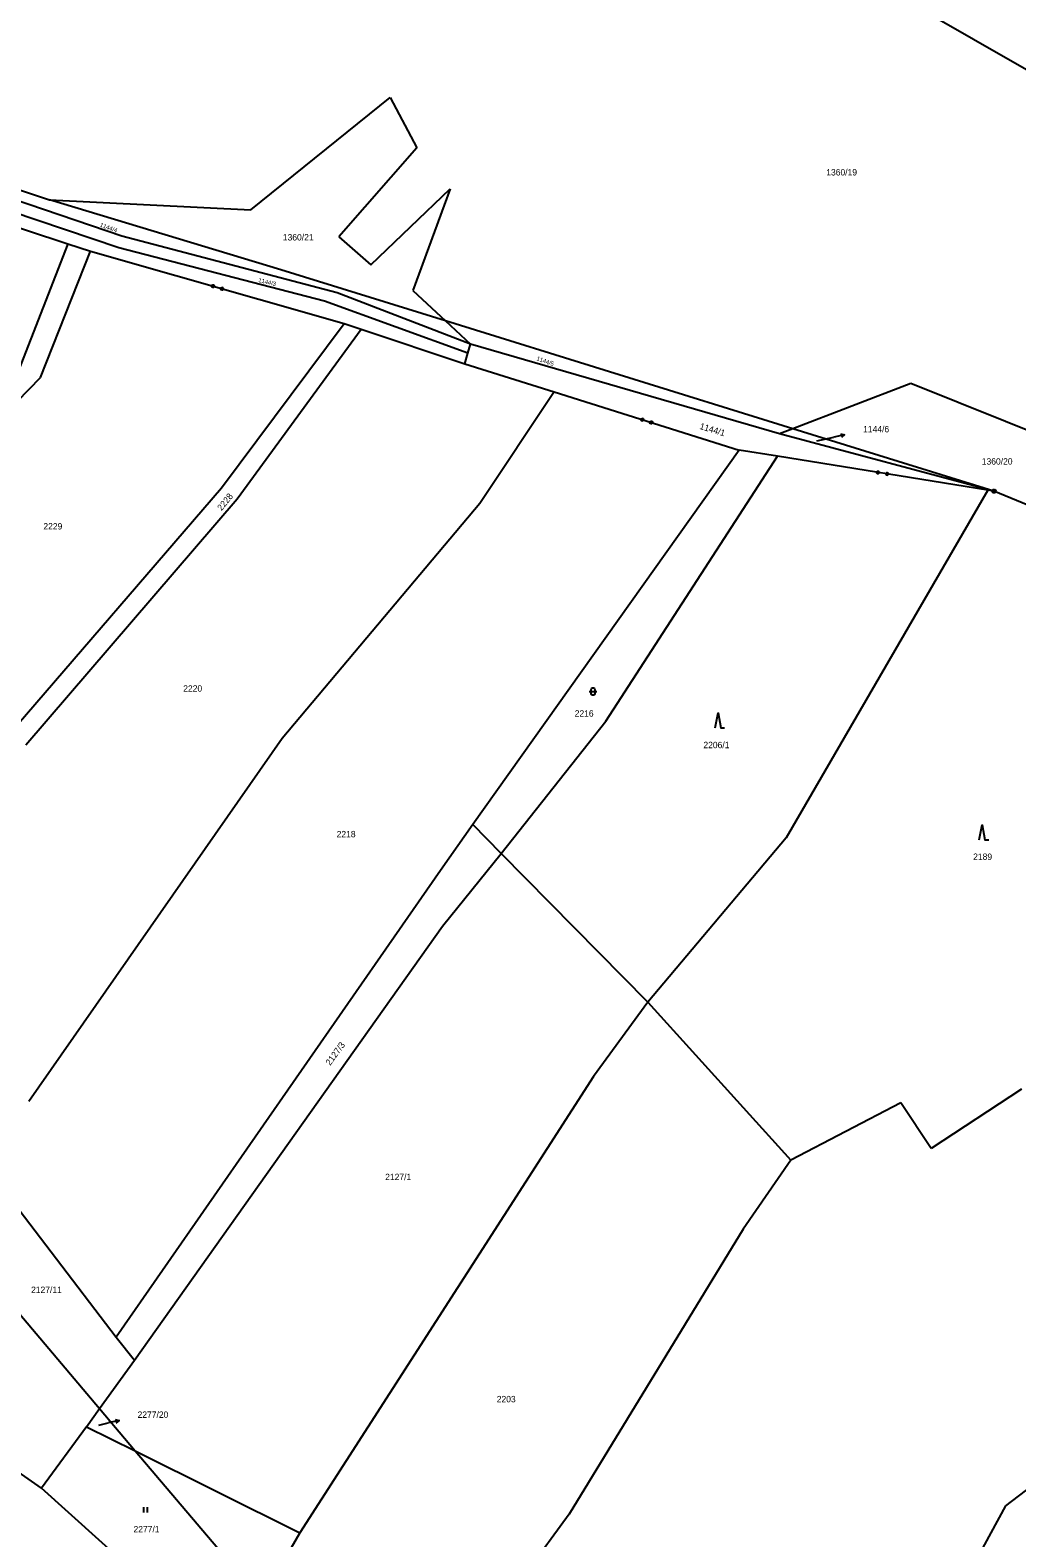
# Model space of a CAD drawing. Extents: x -747792 to -745414, y -1093712 to -1091463.
# Drawn here: x -746345.7 to -746213.9, y -1092850.4 to -1092649.1 of the extents above; entities that cross this region are included whole.
import ezdxf

# ---------------------------------------------------------------- set-up
doc = ezdxf.new("R2010")
doc.units = 0
for name, color, linetype in [('Pracovní_bod JDTM STC_VC', 7, 'Continuous'), ('Pracovní_bod JDTM STC_VC - číslo', 7, 'Continuous'), ('Pracovní_bod NN - výška', 7, 'Continuous'), ('Pracovní_bod polohopisu - výška', 7, 'Continuous'), ('Pracovní_bod VN - výška', 7, 'Continuous')]:
    doc.layers.add(name, color=color, linetype=linetype)

msp = doc.modelspace()

# ---------------------------------------------------------------- linework, layer by layer
at = {"layer": 'Pracovní_bod JDTM STC_VC - číslo'}
for points in [[(-746270.99, -1092737.4), (-746270.35, -1092737.4), (-746269.99, -1092737.4)], [(-746254.16, -1092742.26), (-746253.78, -1092740.26), (-746253.41, -1092742.26), (-746252.91, -1092742.26)], [(-746218.9, -1092757.18), (-746218.52, -1092755.18), (-746218.15, -1092757.18), (-746217.65, -1092757.18)], [(-746330.51, -1092846.31), (-746330.51, -1092847.06)], [(-746330.01, -1092847.06), (-746330.01, -1092846.31)]]:
    msp.add_lwpolyline(points, dxfattribs=at)
msp.add_lwpolyline([(-746270.74, -1092737.15), (-746270.69, -1092737.01), (-746270.57, -1092736.92), (-746270.41, -1092736.92), (-746270.28, -1092737.01), (-746270.23, -1092737.15), (-746270.23, -1092737.65), (-746270.28, -1092737.79), (-746270.41, -1092737.88), (-746270.57, -1092737.88), (-746270.69, -1092737.79), (-746270.74, -1092737.65)], close=True, dxfattribs=at)
at = {"layer": 'Pracovní_bod NN - výška'}
for points in [[(-746138.26, -1092696.87), (-746328.04, -1092588.27)], [(-746333.4, -1092676.58), (-746383.28, -1092659.63)], [(-746382.43, -1092658.53), (-746343.09, -1092671.73)], [(-746316.2, -1092673.08), (-746297.59, -1092658.05)], [(-746297.59, -1092658.05), (-746294, -1092664.76)], [(-746333.8, -1092678.12), (-746384.12, -1092661.15)], [(-746385.1, -1092662.91), (-746340.63, -1092677.59)], [(-746385.1, -1092662.91), (-746340.63, -1092677.59)], [(-746294, -1092664.76), (-746304.42, -1092676.67)], [(-746343.09, -1092671.73), (-746316.2, -1092673.08)], [(-746312.2, -1092681.06), (-746343.09, -1092671.73)], [(-746300.15, -1092680.41), (-746289.57, -1092670.24)], [(-746289.57, -1092670.24), (-746294.55, -1092683.83)], [(-746340.63, -1092677.59), (-746347.23, -1092694.52)], [(-746340.63, -1092677.59), (-746337.61, -1092678.59)], [(-746340.63, -1092677.59), (-746337.61, -1092678.59)], [(-746304.67, -1092684.13), (-746333.4, -1092676.58)], [(-746304.42, -1092676.67), (-746300.15, -1092680.41)], [(-746344.28, -1092695.45), (-746337.61, -1092678.59)], [(-746337.61, -1092678.59), (-746303.71, -1092688.24)], [(-746337.61, -1092678.59), (-746303.71, -1092688.24)], [(-746306.34, -1092685.25), (-746333.8, -1092678.12)], [(-746290.18, -1092687.9), (-746312.2, -1092681.06)], [(-746321.13, -1092683.11), (-746321.07, -1092683.23), (-746321.1, -1092683.36), (-746321.22, -1092683.43), (-746321.35, -1092683.39), (-746321.41, -1092683.27), (-746321.38, -1092683.14), (-746321.26, -1092683.08), (-746321.13, -1092683.11), (-746321.14, -1092683.13), (-746321.26, -1092683.1), (-746321.31, -1092683.13), (-746321.11, -1092683.18), (-746321.09, -1092683.23), (-746321.36, -1092683.15), (-746321.37, -1092683.19), (-746321.1, -1092683.27), (-746321.11, -1092683.31), (-746321.38, -1092683.23), (-746321.39, -1092683.27), (-746321.12, -1092683.35), (-746321.17, -1092683.37), (-746321.36, -1092683.32), (-746321.33, -1092683.37), (-746321.22, -1092683.4)], [(-746321.13, -1092683.11), (-746321.07, -1092683.23), (-746321.1, -1092683.36), (-746321.22, -1092683.43), (-746321.35, -1092683.39), (-746321.41, -1092683.27), (-746321.38, -1092683.14), (-746321.26, -1092683.08), (-746321.13, -1092683.11), (-746321.14, -1092683.13), (-746321.26, -1092683.1), (-746321.31, -1092683.13), (-746321.11, -1092683.18), (-746321.09, -1092683.23), (-746321.36, -1092683.15), (-746321.37, -1092683.19), (-746321.1, -1092683.27), (-746321.11, -1092683.31), (-746321.38, -1092683.23), (-746321.39, -1092683.27), (-746321.12, -1092683.35), (-746321.17, -1092683.37), (-746321.36, -1092683.32), (-746321.33, -1092683.37), (-746321.22, -1092683.4)], [(-746319.93, -1092683.46), (-746319.86, -1092683.57), (-746319.9, -1092683.7), (-746320.02, -1092683.77), (-746320.15, -1092683.73), (-746320.21, -1092683.62), (-746320.18, -1092683.49), (-746320.06, -1092683.42), (-746319.93, -1092683.46), (-746319.95, -1092683.47), (-746320.06, -1092683.44), (-746320.11, -1092683.47), (-746319.92, -1092683.52), (-746319.89, -1092683.57), (-746320.16, -1092683.49), (-746320.17, -1092683.53), (-746319.9, -1092683.61), (-746319.92, -1092683.65), (-746320.18, -1092683.57), (-746320.2, -1092683.61), (-746319.93, -1092683.69), (-746319.98, -1092683.71), (-746320.17, -1092683.66), (-746320.14, -1092683.71), (-746320.03, -1092683.74)], [(-746319.93, -1092683.46), (-746319.86, -1092683.57), (-746319.9, -1092683.7), (-746320.02, -1092683.77), (-746320.15, -1092683.73), (-746320.21, -1092683.62), (-746320.18, -1092683.49), (-746320.06, -1092683.42), (-746319.93, -1092683.46), (-746319.95, -1092683.47), (-746320.06, -1092683.44), (-746320.11, -1092683.47), (-746319.92, -1092683.52), (-746319.89, -1092683.57), (-746320.16, -1092683.49), (-746320.17, -1092683.53), (-746319.9, -1092683.61), (-746319.92, -1092683.65), (-746320.18, -1092683.57), (-746320.2, -1092683.61), (-746319.93, -1092683.69), (-746319.98, -1092683.71), (-746320.17, -1092683.66), (-746320.14, -1092683.71), (-746320.03, -1092683.74)], [(-746287.19, -1092692.2), (-746306.34, -1092685.25)], [(-746286.85, -1092691), (-746304.67, -1092684.13)], [(-746294.55, -1092683.83), (-746290.18, -1092687.9)], [(-746320.11, -1092710.19), (-746303.71, -1092688.24)], [(-746318.02, -1092711.64), (-746301.45, -1092689)], [(-746303.71, -1092688.24), (-746301.45, -1092689)], [(-746303.71, -1092688.24), (-746301.45, -1092689)], [(-746301.45, -1092689), (-746287.61, -1092693.64)], [(-746301.45, -1092689), (-746287.61, -1092693.64)], [(-746290.18, -1092687.9), (-746286.85, -1092691)], [(-746243.81, -1092702.3), (-746290.18, -1092687.9)], [(-746287.19, -1092692.2), (-746286.85, -1092691)], [(-746245.6, -1092702.98), (-746286.85, -1092691)], [(-746287.61, -1092693.64), (-746287.19, -1092692.2)], [(-746287.61, -1092693.64), (-746275.7, -1092697.38)], [(-746287.61, -1092693.64), (-746275.7, -1092697.38)], [(-746368.82, -1092720.63), (-746344.28, -1092695.45)], [(-746275.7, -1092697.38), (-746285.63, -1092712.3)], [(-746275.7, -1092697.38), (-746250.98, -1092705.15)], [(-746275.7, -1092697.38), (-746250.98, -1092705.15)], [(-746228.03, -1092696.26), (-746243.81, -1092702.3)], [(-746196.64, -1092708.86), (-746228.03, -1092696.26)], [(-746263.8, -1092700.95), (-746263.74, -1092701.07), (-746263.78, -1092701.2), (-746263.9, -1092701.26), (-746264.03, -1092701.22), (-746264.09, -1092701.1), (-746264.05, -1092700.97), (-746263.93, -1092700.91), (-746263.8, -1092700.95), (-746263.81, -1092700.97), (-746263.93, -1092700.93), (-746263.98, -1092700.96), (-746263.79, -1092701.02), (-746263.76, -1092701.07), (-746264.03, -1092700.99), (-746264.04, -1092701.02), (-746263.77, -1092701.11), (-746263.78, -1092701.15), (-746264.05, -1092701.06), (-746264.06, -1092701.1), (-746263.8, -1092701.18), (-746263.85, -1092701.21), (-746264.04, -1092701.15), (-746264.01, -1092701.2), (-746263.9, -1092701.24)], [(-746263.8, -1092700.95), (-746263.74, -1092701.07), (-746263.78, -1092701.2), (-746263.9, -1092701.26), (-746264.03, -1092701.22), (-746264.09, -1092701.1), (-746264.05, -1092700.97), (-746263.93, -1092700.91), (-746263.8, -1092700.95), (-746263.81, -1092700.97), (-746263.93, -1092700.93), (-746263.98, -1092700.96), (-746263.79, -1092701.02), (-746263.76, -1092701.07), (-746264.03, -1092700.99), (-746264.04, -1092701.02), (-746263.77, -1092701.11), (-746263.78, -1092701.15), (-746264.05, -1092701.06), (-746264.06, -1092701.1), (-746263.8, -1092701.18), (-746263.85, -1092701.21), (-746264.04, -1092701.15), (-746264.01, -1092701.2), (-746263.9, -1092701.24)], [(-746262.61, -1092701.33), (-746262.55, -1092701.45), (-746262.59, -1092701.57), (-746262.71, -1092701.64), (-746262.84, -1092701.6), (-746262.9, -1092701.48), (-746262.86, -1092701.35), (-746262.74, -1092701.29), (-746262.61, -1092701.33), (-746262.63, -1092701.34), (-746262.74, -1092701.31), (-746262.79, -1092701.33), (-746262.6, -1092701.39), (-746262.58, -1092701.44), (-746262.85, -1092701.36), (-746262.86, -1092701.4), (-746262.59, -1092701.48), (-746262.6, -1092701.52), (-746262.87, -1092701.43), (-746262.88, -1092701.47), (-746262.61, -1092701.56), (-746262.66, -1092701.58), (-746262.85, -1092701.52), (-746262.83, -1092701.57), (-746262.71, -1092701.61)], [(-746262.61, -1092701.33), (-746262.55, -1092701.45), (-746262.59, -1092701.57), (-746262.71, -1092701.64), (-746262.84, -1092701.6), (-746262.9, -1092701.48), (-746262.86, -1092701.35), (-746262.74, -1092701.29), (-746262.61, -1092701.33), (-746262.63, -1092701.34), (-746262.74, -1092701.31), (-746262.79, -1092701.33), (-746262.6, -1092701.39), (-746262.58, -1092701.44), (-746262.85, -1092701.36), (-746262.86, -1092701.4), (-746262.59, -1092701.48), (-746262.6, -1092701.52), (-746262.87, -1092701.43), (-746262.88, -1092701.47), (-746262.61, -1092701.56), (-746262.66, -1092701.58), (-746262.85, -1092701.52), (-746262.83, -1092701.57), (-746262.71, -1092701.61)], [(-746243.81, -1092702.3), (-746245.6, -1092702.98)], [(-746216.96, -1092710.63), (-746245.6, -1092702.98)], [(-746216.96, -1092710.63), (-746243.81, -1092702.3)], [(-746250.98, -1092705.15), (-746286.54, -1092755.17)], [(-746268.8, -1092741.33), (-746245.86, -1092705.97)], [(-746245.86, -1092705.97), (-746250.98, -1092705.15)], [(-746245.86, -1092705.97), (-746250.98, -1092705.15)], [(-746217.76, -1092710.5), (-746245.86, -1092705.97)], [(-746217.76, -1092710.5), (-746245.86, -1092705.97)], [(-746232.54, -1092708.28), (-746232.62, -1092708.17), (-746232.6, -1092708.04), (-746232.49, -1092707.96), (-746232.36, -1092707.98), (-746232.28, -1092708.09), (-746232.3, -1092708.22), (-746232.41, -1092708.3), (-746232.54, -1092708.28), (-746232.52, -1092708.26), (-746232.4, -1092708.28), (-746232.36, -1092708.25), (-746232.56, -1092708.22), (-746232.59, -1092708.17), (-746232.31, -1092708.21), (-746232.31, -1092708.18), (-746232.58, -1092708.13), (-746232.58, -1092708.09), (-746232.3, -1092708.14), (-746232.29, -1092708.1), (-746232.57, -1092708.05), (-746232.52, -1092708.02), (-746232.33, -1092708.05), (-746232.36, -1092708), (-746232.48, -1092707.99)], [(-746232.54, -1092708.28), (-746232.62, -1092708.17), (-746232.6, -1092708.04), (-746232.49, -1092707.96), (-746232.36, -1092707.98), (-746232.28, -1092708.09), (-746232.3, -1092708.22), (-746232.41, -1092708.3), (-746232.54, -1092708.28), (-746232.52, -1092708.26), (-746232.4, -1092708.28), (-746232.36, -1092708.25), (-746232.56, -1092708.22), (-746232.59, -1092708.17), (-746232.31, -1092708.21), (-746232.31, -1092708.18), (-746232.58, -1092708.13), (-746232.58, -1092708.09), (-746232.3, -1092708.14), (-746232.29, -1092708.1), (-746232.57, -1092708.05), (-746232.52, -1092708.02), (-746232.33, -1092708.05), (-746232.36, -1092708), (-746232.48, -1092707.99)], [(-746231.31, -1092708.48), (-746231.39, -1092708.37), (-746231.36, -1092708.24), (-746231.26, -1092708.16), (-746231.12, -1092708.18), (-746231.04, -1092708.29), (-746231.07, -1092708.42), (-746231.17, -1092708.5), (-746231.31, -1092708.48), (-746231.3, -1092708.46), (-746231.18, -1092708.48), (-746231.13, -1092708.45), (-746231.33, -1092708.41), (-746231.37, -1092708.37), (-746231.09, -1092708.41), (-746231.08, -1092708.37), (-746231.36, -1092708.33), (-746231.35, -1092708.29), (-746231.08, -1092708.33), (-746231.07, -1092708.29), (-746231.35, -1092708.25), (-746231.3, -1092708.22), (-746231.1, -1092708.25), (-746231.14, -1092708.2), (-746231.25, -1092708.18)], [(-746231.31, -1092708.48), (-746231.39, -1092708.37), (-746231.36, -1092708.24), (-746231.26, -1092708.16), (-746231.12, -1092708.18), (-746231.04, -1092708.29), (-746231.07, -1092708.42), (-746231.17, -1092708.5), (-746231.31, -1092708.48), (-746231.3, -1092708.46), (-746231.18, -1092708.48), (-746231.13, -1092708.45), (-746231.33, -1092708.41), (-746231.37, -1092708.37), (-746231.09, -1092708.41), (-746231.08, -1092708.37), (-746231.36, -1092708.33), (-746231.35, -1092708.29), (-746231.08, -1092708.33), (-746231.07, -1092708.29), (-746231.35, -1092708.25), (-746231.3, -1092708.22), (-746231.1, -1092708.25), (-746231.14, -1092708.2), (-746231.25, -1092708.18)], [(-746348.66, -1092743.33), (-746320.11, -1092710.19)], [(-746346.23, -1092744.52), (-746318.02, -1092711.64)], [(-746217.76, -1092710.5), (-746244.7, -1092756.95)], [(-746216.96, -1092710.63), (-746217.76, -1092710.5)], [(-746216.96, -1092710.63), (-746217.76, -1092710.5)], [(-746198.49, -1092718.25), (-746216.96, -1092710.63)], [(-746198.49, -1092718.25), (-746216.96, -1092710.63)], [(-746285.63, -1092712.3), (-746311.99, -1092743.66)], [(-746282.77, -1092759.01), (-746268.8, -1092741.33)], [(-746311.99, -1092743.66), (-746345.85, -1092792.16)], [(-746286.54, -1092755.17), (-746290.86, -1092761.28)], [(-746282.77, -1092759.01), (-746286.54, -1092755.17)], [(-746244.7, -1092756.95), (-746263.17, -1092778.89)], [(-746290.58, -1092768.73), (-746282.77, -1092759.01)], [(-746263.17, -1092778.89), (-746282.77, -1092759.01)], [(-746290.86, -1092761.28), (-746334.18, -1092823.61)], [(-746331.73, -1092826.69), (-746290.58, -1092768.73)], [(-746263.17, -1092778.89), (-746270.43, -1092788.81)], [(-746263.17, -1092778.89), (-746244.06, -1092799.98)], [(-746270.43, -1092788.81), (-746309.64, -1092849.74)], [(-746213.27, -1092790.51), (-746225.33, -1092798.43)], [(-746229.38, -1092792.33), (-746244.06, -1092799.98)], [(-746225.33, -1092798.43), (-746229.38, -1092792.33)], [(-746244.06, -1092799.98), (-746250.46, -1092809.19)], [(-746351.58, -1092800.85), (-746334.18, -1092823.61)], [(-746250.46, -1092809.19), (-746273.68, -1092847.28)], [(-746349.98, -1092817.13), (-746336.42, -1092833.17)], [(-746334.18, -1092823.61), (-746331.73, -1092826.69)], [(-746344.15, -1092843.81), (-746369.83, -1092825.85)], [(-746336.42, -1092833.17), (-746331.73, -1092826.69)], [(-746194.25, -1092830.02), (-746215.41, -1092846.14)], [(-746338.13, -1092835.58), (-746336.42, -1092833.17)], [(-746336.42, -1092833.17), (-746331.63, -1092838.81)], [(-746338.13, -1092835.58), (-746344.15, -1092843.81)], [(-746338.13, -1092835.58), (-746331.63, -1092838.81)], [(-746331.63, -1092838.81), (-746309.64, -1092849.74)], [(-746331.63, -1092838.81), (-746315.08, -1092858.29)], [(-746321.2, -1092864.48), (-746344.15, -1092843.81)], [(-746215.41, -1092846.14), (-746238.92, -1092889.41)], [(-746273.68, -1092847.28), (-746290.62, -1092870.51)], [(-746309.64, -1092849.74), (-746313.6, -1092856.63)]]:
    msp.add_lwpolyline(points, dxfattribs=at)
at = {"layer": 'Pracovní_bod polohopisu - výška'}
for points in [[(-746240.59, -1092703.93), (-746238.35, -1092703.43)], [(-746236.89, -1092703.1), (-746238.35, -1092703.43)], [(-746237.43, -1092702.97), (-746236.89, -1092703.1), (-746237.32, -1092703.46)], [(-746333.78, -1092834.74), (-746335.24, -1092835.08)], [(-746334.32, -1092834.61), (-746333.78, -1092834.74), (-746334.21, -1092835.1)], [(-746336.49, -1092835.37), (-746335.24, -1092835.08)]]:
    msp.add_lwpolyline(points, dxfattribs=at)
at = {"layer": 'Pracovní_bod VN - výška'}
msp.add_lwpolyline([(-746216.89, -1092710.39), (-746216.76, -1092710.48), (-746216.71, -1092710.63), (-746216.76, -1092710.77), (-746216.89, -1092710.87), (-746217.03, -1092710.87), (-746217.16, -1092710.77), (-746217.21, -1092710.63), (-746217.16, -1092710.48), (-746217.03, -1092710.39)], close=True, dxfattribs=at)
msp.add_lwpolyline([(-746216.98, -1092710.63), (-746216.93, -1092710.63)], dxfattribs=at)

# ---------------------------------------------------------------- texts
at = {"layer": 'Pracovní_bod JDTM STC_VC'}
for s, p in [('1360/19', (-746239.34, -1092668.47)), ('1360/21', (-746311.92, -1092677.15)), ('1360/20', (-746218.57, -1092707.08)), ('2229', (-746343.9, -1092715.75)), ('2220', (-746325.22, -1092737.41)), ('2216', (-746272.94, -1092740.74)), ('2206/1', (-746255.75, -1092744.96)), ('2218', (-746304.73, -1092756.86)), ('2189', (-746219.72, -1092759.88)), ('2127/1', (-746298.25, -1092802.65)), ('2127/11', (-746345.54, -1092817.72)), ('2203', (-746283.35, -1092832.32)), ('2277/1', (-746331.86, -1092849.69))]:
    msp.add_text(s, height=0.85, dxfattribs=at).set_placement(p)
for s, height, rotation, p in [('1144/4', 0.57, 339.8786, (-746336.4, -1092675.28)), ('1144/3', 0.57, 346.353, (-746315.24, -1092682.69)), ('1144/5', 0.57, 340.6234, (-746278.09, -1092693.14)), ('1144/1', 0.85, 343.2017, (-746256.32, -1092702.31)), ('1144/6', 0.05, 341.712, (-746240.69, -1092703.9)), ('2228', 0.85, 51.1078, (-746320.1, -1092713.31)), ('2127/3', 0.85, 53.9153, (-746305.6, -1092787.41)), ('2277/20', 0.05, 334.0344, (-746336.62, -1092835.31))]:
    msp.add_text(s, height=height, rotation=rotation, dxfattribs=at).set_placement(p)
at = {"layer": 'Pracovní_bod polohopisu - výška'}
for s, p in [('1144/6', (-746234.42, -1092702.78)), ('2277/20', (-746331.32, -1092834.4))]:
    msp.add_text(s, height=0.85, dxfattribs=at).set_placement(p)

doc.saveas('drawing.dxf')
